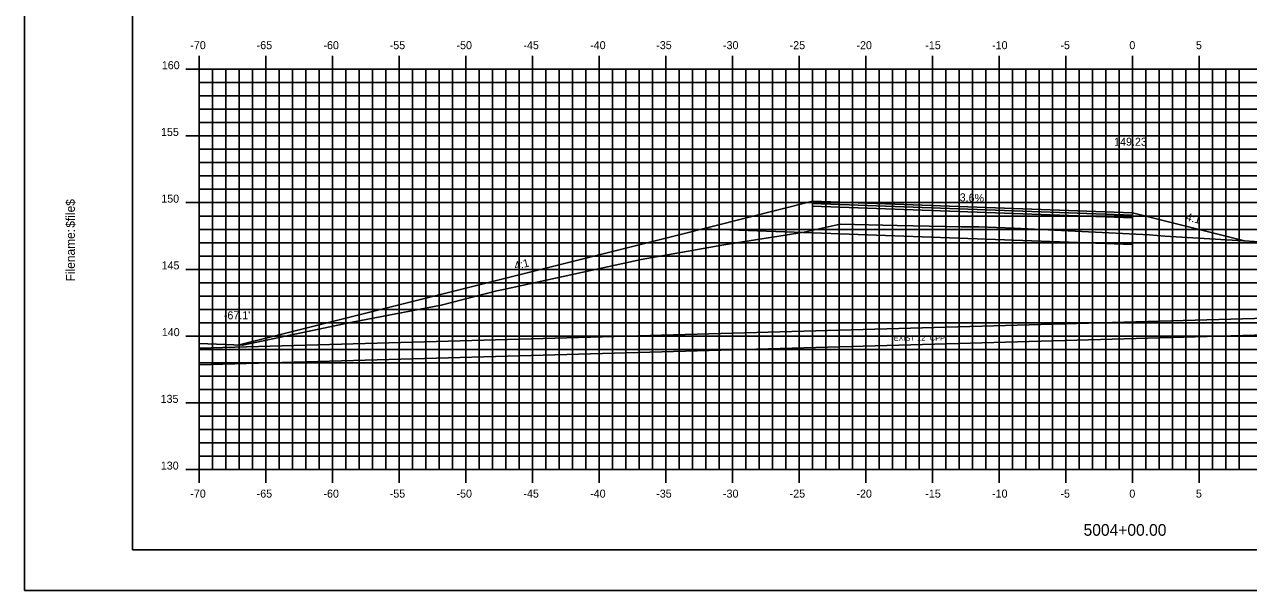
# Model space of a CAD drawing. Extents: x 852082 to 852254, y 365876 to 365986.
# Drawn here: x 852082.1 to 852173.9, y 365875.8 to 365918.2 of the extents above; entities that cross this region are included whole.
import ezdxf

# ---------------------------------------------------------------- set-up
doc = ezdxf.new("R2010")
doc.units = 0
for name, color, linetype in [('ANNOTATION', 7, 'Continuous'), ('BORDER', 7, 'Continuous'), ('D_Drainage_Culvert', 7, 'Continuous'), ('D_Roadway_Centerline', 7, 'Continuous'), ('D_Roadway_Centerline_Text', 7, 'Continuous'), ('D_Roadway_Edge_TW', 7, 'Continuous'), ('D_Roadway_FinishedGrade', 7, 'Continuous'), ('D_Roadway_Pavement', 7, 'Continuous'), ('D_Roadway_SlopeLines', 7, 'Continuous'), ('D_Roadway_SubGrade', 7, 'Continuous'), ('D_Text_Monospaced', 7, 'Continuous'), ('D_Text_Standard', 7, 'Continuous'), ('H_V ANNOTATION', 7, 'Continuous'), ('MAJOR', 7, 'Continuous'), ('MINOR', 7, 'Continuous'), ('PLOT BOUNDARY', 7, 'Continuous'), ('S_Roadway_Centerline', 7, 'Continuous')]:
    doc.layers.add(name, color=color, linetype=linetype)

msp = doc.modelspace()

# ---------------------------------------------------------------- linework, layer by layer
at = {"layer": 'BORDER'}
msp.add_lwpolyline([(852090.168, 365878.833), (852250.168, 365878.833), (852250.168, 365983.833), (852090.168, 365983.833)], close=True, dxfattribs=at)
at = {"layer": 'D_Drainage_Culvert'}
msp.add_lwpolyline([(852095.168, 365892.674), (852204.568, 365895.764), (852204.533, 365897.014), (852095.168, 365893.925)], dxfattribs=at)
at = {"layer": 'D_Roadway_Centerline'}
msp.add_lwpolyline([(852098.064, 365894.159), (852131.168, 365902.435), (852141.168, 365904.935), (852165.168, 365904.067), (852173.559, 365901.969)], dxfattribs=at)
at = {"layer": 'D_Roadway_Edge_TW'}
msp.add_lwpolyline([(852141.168, 365904.935), (852165.168, 365904.067), (852165.168, 365903.9), (852141.168, 365904.768)], close=True, dxfattribs=at)
at = {"layer": 'D_Roadway_FinishedGrade'}
msp.add_line((852141.168, 365902.568), (852132.898, 365902.867), dxfattribs=at)
at = {"layer": 'D_Roadway_Pavement'}
msp.add_lwpolyline([(852141.168, 365904.768), (852165.168, 365903.9), (852165.168, 365903.7), (852141.168, 365904.568)], close=True, dxfattribs=at)
msp.add_lwpolyline([(852165.168, 365903.9), (852165.168, 365903.7)], dxfattribs=at)
msp.add_lwpolyline([(852165.168, 365903.9), (852165.168, 365903.7)], dxfattribs=at)
at = {"layer": 'D_Roadway_SlopeLines'}
for points in [[(852141.168, 365904.935), (852131.168, 365902.435), (852098.064, 365894.159)], [(852165.168, 365904.067), (852173.559, 365901.969)]]:
    msp.add_lwpolyline(points, dxfattribs=at)
at = {"layer": 'D_Roadway_SubGrade'}
msp.add_lwpolyline([(852141.168, 365904.568), (852165.168, 365903.7), (852165.168, 365901.7), (852141.168, 365902.568)], dxfattribs=at)
at = {"layer": 'MAJOR'}
for p, q in [((852095.168, 365915.835), (852095.168, 365914.833)), ((852100.168, 365915.835), (852100.168, 365914.833)), ((852105.168, 365915.835), (852105.168, 365914.833)), ((852110.168, 365915.835), (852110.168, 365914.833)), ((852115.168, 365915.835), (852115.168, 365914.833)), ((852120.168, 365915.835), (852120.168, 365914.833)), ((852125.168, 365915.835), (852125.168, 365914.833)), ((852130.168, 365915.835), (852130.168, 365914.833)), ((852135.168, 365915.835), (852135.168, 365914.833)), ((852140.168, 365915.835), (852140.168, 365914.833)), ((852145.168, 365915.835), (852145.168, 365914.833)), ((852150.168, 365915.835), (852150.168, 365914.833)), ((852155.168, 365915.835), (852155.168, 365914.833)), ((852160.168, 365915.835), (852160.168, 365914.833)), ((852165.168, 365915.835), (852165.168, 365914.833)), ((852170.168, 365915.835), (852170.168, 365914.833)), ((852094.166, 365914.833), (852095.168, 365914.833)), ((852095.168, 365914.833), (852235.168, 365914.833)), ((852095.168, 365884.833), (852095.168, 365914.833)), ((852095.168, 365884.833), (852095.168, 365914.833)), ((852095.168, 365914.833), (852235.168, 365914.833)), ((852100.168, 365884.833), (852100.168, 365914.833)), ((852105.168, 365884.833), (852105.168, 365914.833)), ((852110.168, 365884.833), (852110.168, 365914.833)), ((852115.168, 365884.833), (852115.168, 365914.833)), ((852120.168, 365884.833), (852120.168, 365914.833)), ((852125.168, 365884.833), (852125.168, 365914.833)), ((852130.168, 365884.833), (852130.168, 365914.833)), ((852135.168, 365884.833), (852135.168, 365914.833)), ((852140.168, 365884.833), (852140.168, 365914.833)), ((852145.168, 365884.833), (852145.168, 365914.833)), ((852150.168, 365884.833), (852150.168, 365914.833)), ((852155.168, 365884.833), (852155.168, 365914.833)), ((852160.168, 365884.833), (852160.168, 365914.833)), ((852165.168, 365884.833), (852165.168, 365914.833)), ((852170.168, 365884.833), (852170.168, 365914.833)), ((852094.166, 365909.833), (852095.168, 365909.833)), ((852095.168, 365909.833), (852235.168, 365909.833)), ((852094.166, 365904.833), (852095.168, 365904.833)), ((852095.168, 365904.833), (852235.168, 365904.833)), ((852094.166, 365899.833), (852095.168, 365899.833)), ((852095.168, 365899.833), (852235.168, 365899.833)), ((852094.166, 365894.833), (852095.168, 365894.833)), ((852095.168, 365894.833), (852235.168, 365894.833)), ((852094.166, 365889.833), (852095.168, 365889.833)), ((852095.168, 365889.833), (852235.168, 365889.833)), ((852094.166, 365884.833), (852095.168, 365884.833)), ((852095.168, 365884.833), (852235.168, 365884.833)), ((852095.168, 365884.833), (852235.168, 365884.833)), ((852095.168, 365883.831), (852095.168, 365884.833)), ((852100.168, 365883.831), (852100.168, 365884.833)), ((852105.168, 365883.831), (852105.168, 365884.833)), ((852110.168, 365883.831), (852110.168, 365884.833)), ((852115.168, 365883.831), (852115.168, 365884.833)), ((852120.168, 365883.831), (852120.168, 365884.833)), ((852125.168, 365883.831), (852125.168, 365884.833)), ((852130.168, 365883.831), (852130.168, 365884.833)), ((852135.168, 365883.831), (852135.168, 365884.833)), ((852140.168, 365883.831), (852140.168, 365884.833)), ((852145.168, 365883.831), (852145.168, 365884.833)), ((852150.168, 365883.831), (852150.168, 365884.833)), ((852155.168, 365883.831), (852155.168, 365884.833)), ((852160.168, 365883.831), (852160.168, 365884.833)), ((852165.168, 365883.831), (852165.168, 365884.833)), ((852170.168, 365883.831), (852170.168, 365884.833))]:
    msp.add_line(p, q, dxfattribs=at)
at = {"layer": 'MINOR'}
for p, q in [((852096.168, 365884.833), (852096.168, 365914.833)), ((852097.168, 365884.833), (852097.168, 365914.833)), ((852098.168, 365884.833), (852098.168, 365914.833)), ((852099.168, 365884.833), (852099.168, 365914.833)), ((852101.168, 365884.833), (852101.168, 365914.833)), ((852102.168, 365884.833), (852102.168, 365914.833)), ((852103.168, 365884.833), (852103.168, 365914.833)), ((852104.168, 365884.833), (852104.168, 365914.833)), ((852106.168, 365884.833), (852106.168, 365914.833)), ((852107.168, 365884.833), (852107.168, 365914.833)), ((852108.168, 365884.833), (852108.168, 365914.833)), ((852109.168, 365884.833), (852109.168, 365914.833)), ((852111.168, 365884.833), (852111.168, 365914.833)), ((852112.168, 365884.833), (852112.168, 365914.833)), ((852113.168, 365884.833), (852113.168, 365914.833)), ((852114.168, 365884.833), (852114.168, 365914.833)), ((852116.168, 365884.833), (852116.168, 365914.833)), ((852117.168, 365884.833), (852117.168, 365914.833)), ((852118.168, 365884.833), (852118.168, 365914.833)), ((852119.168, 365884.833), (852119.168, 365914.833)), ((852121.168, 365884.833), (852121.168, 365914.833)), ((852122.168, 365884.833), (852122.168, 365914.833)), ((852123.168, 365884.833), (852123.168, 365914.833)), ((852124.168, 365884.833), (852124.168, 365914.833)), ((852126.168, 365884.833), (852126.168, 365914.833)), ((852127.168, 365884.833), (852127.168, 365914.833)), ((852128.168, 365884.833), (852128.168, 365914.833)), ((852129.168, 365884.833), (852129.168, 365914.833)), ((852131.168, 365884.833), (852131.168, 365914.833)), ((852132.168, 365884.833), (852132.168, 365914.833)), ((852133.168, 365884.833), (852133.168, 365914.833)), ((852134.168, 365884.833), (852134.168, 365914.833)), ((852136.168, 365884.833), (852136.168, 365914.833)), ((852137.168, 365884.833), (852137.168, 365914.833)), ((852138.168, 365884.833), (852138.168, 365914.833)), ((852139.168, 365884.833), (852139.168, 365914.833)), ((852141.168, 365884.833), (852141.168, 365914.833)), ((852142.168, 365884.833), (852142.168, 365914.833)), ((852143.168, 365884.833), (852143.168, 365914.833)), ((852144.168, 365884.833), (852144.168, 365914.833)), ((852146.168, 365884.833), (852146.168, 365914.833)), ((852147.168, 365884.833), (852147.168, 365914.833)), ((852148.168, 365884.833), (852148.168, 365914.833)), ((852149.168, 365884.833), (852149.168, 365914.833)), ((852151.168, 365884.833), (852151.168, 365914.833)), ((852152.168, 365884.833), (852152.168, 365914.833)), ((852153.168, 365884.833), (852153.168, 365914.833)), ((852154.168, 365884.833), (852154.168, 365914.833)), ((852156.168, 365884.833), (852156.168, 365914.833)), ((852157.168, 365884.833), (852157.168, 365914.833)), ((852158.168, 365884.833), (852158.168, 365914.833)), ((852159.168, 365884.833), (852159.168, 365914.833)), ((852161.168, 365884.833), (852161.168, 365914.833)), ((852162.168, 365884.833), (852162.168, 365914.833)), ((852163.168, 365884.833), (852163.168, 365914.833)), ((852164.168, 365884.833), (852164.168, 365914.833)), ((852166.168, 365884.833), (852166.168, 365914.833)), ((852167.168, 365884.833), (852167.168, 365914.833)), ((852168.168, 365884.833), (852168.168, 365914.833)), ((852169.168, 365884.833), (852169.168, 365914.833)), ((852171.168, 365884.833), (852171.168, 365914.833)), ((852172.168, 365884.833), (852172.168, 365914.833)), ((852173.168, 365884.833), (852173.168, 365914.833)), ((852095.168, 365913.833), (852235.168, 365913.833)), ((852095.168, 365913.833), (852096.17, 365913.833)), ((852095.168, 365912.833), (852235.168, 365912.833)), ((852095.168, 365912.833), (852096.17, 365912.833)), ((852095.168, 365911.833), (852235.168, 365911.833)), ((852095.168, 365911.833), (852096.17, 365911.833)), ((852095.168, 365910.833), (852235.168, 365910.833)), ((852095.168, 365910.833), (852096.17, 365910.833)), ((852095.168, 365908.833), (852235.168, 365908.833)), ((852095.168, 365908.833), (852096.17, 365908.833)), ((852095.168, 365907.833), (852235.168, 365907.833)), ((852095.168, 365907.833), (852096.17, 365907.833)), ((852095.168, 365906.833), (852235.168, 365906.833)), ((852095.168, 365906.833), (852096.17, 365906.833)), ((852095.168, 365905.833), (852235.168, 365905.833)), ((852095.168, 365905.833), (852096.17, 365905.833)), ((852095.168, 365903.833), (852235.168, 365903.833)), ((852095.168, 365903.833), (852096.17, 365903.833)), ((852095.168, 365902.833), (852235.168, 365902.833)), ((852095.168, 365902.833), (852096.17, 365902.833)), ((852095.168, 365901.833), (852235.168, 365901.833)), ((852095.168, 365901.833), (852096.17, 365901.833)), ((852095.168, 365900.833), (852235.168, 365900.833)), ((852095.168, 365900.833), (852096.17, 365900.833)), ((852095.168, 365898.833), (852235.168, 365898.833)), ((852095.168, 365898.833), (852096.17, 365898.833)), ((852095.168, 365897.833), (852235.168, 365897.833)), ((852095.168, 365897.833), (852096.17, 365897.833)), ((852095.168, 365896.833), (852235.168, 365896.833)), ((852095.168, 365896.833), (852096.17, 365896.833)), ((852095.168, 365895.833), (852235.168, 365895.833)), ((852095.168, 365895.833), (852096.17, 365895.833)), ((852095.168, 365893.833), (852235.168, 365893.833)), ((852095.168, 365893.833), (852096.17, 365893.833)), ((852095.168, 365892.833), (852235.168, 365892.833)), ((852095.168, 365892.833), (852096.17, 365892.833)), ((852095.168, 365891.833), (852235.168, 365891.833)), ((852095.168, 365891.833), (852096.17, 365891.833)), ((852095.168, 365890.833), (852235.168, 365890.833)), ((852095.168, 365890.833), (852096.17, 365890.833)), ((852095.168, 365888.833), (852235.168, 365888.833)), ((852095.168, 365888.833), (852096.17, 365888.833)), ((852095.168, 365887.833), (852235.168, 365887.833)), ((852095.168, 365887.833), (852096.17, 365887.833)), ((852095.168, 365886.833), (852235.168, 365886.833)), ((852095.168, 365886.833), (852096.17, 365886.833)), ((852095.168, 365885.833), (852235.168, 365885.833)), ((852095.168, 365885.833), (852096.17, 365885.833))]:
    msp.add_line(p, q, dxfattribs=at)
at = {"layer": 'PLOT BOUNDARY'}
msp.add_lwpolyline([(852082.075, 365875.774), (852252.075, 365875.774), (852252.075, 365985.774), (852082.075, 365985.774)], close=True, dxfattribs=at)
at = {"layer": 'S_Roadway_Centerline'}
msp.add_lwpolyline([(852095.168, 365894.275), (852098.427, 365894.144), (852106.658, 365895.867), (852113.325, 365897.157), (852117.505, 365898.216), (852117.991, 365898.323), (852128.33, 365900.575), (852134.515, 365901.68), (852140.531, 365902.632), (852143.245, 365903.216), (852147.519, 365903.122), (852152.325, 365903.031), (852153.64, 365903.026), (852156.302, 365902.922), (852161.358, 365902.66), (852166.428, 365902.412), (852167.58, 365902.33), (852175.592, 365901.847)], dxfattribs=at)

# ---------------------------------------------------------------- texts
at = {"layer": 'ANNOTATION'}
for s, rotation, p in [('3.6%', 357.92852, (852152.194, 365904.937)), ('4:1', 345.96376, (852169.116, 365903.511)), ('4:1', 14.03624, (852118.884, 365899.795))]:
    msp.add_text(s, height=0.6, rotation=rotation, dxfattribs=at).set_placement(p)
at = {"layer": 'BORDER'}
for s, p in [('$file$', (852085.853, 365902.959)), ('Filename:', (852085.853, 365898.932))]:
    msp.add_text(s, height=0.6696, rotation=90, dxfattribs=at).set_placement(p)
at = {"layer": 'D_Roadway_Centerline_Text'}
msp.add_text('149.23', height=0.6, dxfattribs=at).set_placement((852163.785, 365909.099))
at = {"layer": 'D_Text_Monospaced'}
msp.add_text('EXIST 12" CPP', height=0.39998, dxfattribs=at).set_placement((852147.257, 365894.494))
at = {"layer": 'D_Text_Standard'}
msp.add_text("-67.1'", height=0.6, dxfattribs=at).set_placement((852097.024, 365896.095))
at = {"layer": 'H_V ANNOTATION'}
for s, height, p in [('-70', 0.6, (852094.51, 365916.333)), ('-65', 0.6, (852099.486, 365916.333)), ('-60', 0.6, (852104.494, 365916.333)), ('-55', 0.6, (852109.464, 365916.333)), ('-50', 0.6, (852114.472, 365916.333)), ('-45', 0.6, (852119.486, 365916.333)), ('-40', 0.6, (852124.494, 365916.333)), ('-35', 0.6, (852129.448, 365916.333)), ('-30', 0.6, (852134.456, 365916.333)), ('-25', 0.6, (852139.454, 365916.333)), ('-20', 0.6, (852144.462, 365916.333)), ('-15', 0.6, (852149.625, 365916.333)), ('-10', 0.6, (852154.633, 365916.333)), ('-5', 0.6, (852159.759, 365916.333)), ('0', 0.6, (852164.927, 365916.333)), ('5', 0.6, (852169.919, 365916.333)), ('160', 0.6, (852092.373, 365914.833)), ('155', 0.6, (852092.314, 365909.833)), ('150', 0.6, (852092.33, 365904.833)), ('145', 0.6, (852092.357, 365899.833)), ('140', 0.6, (852092.373, 365894.833)), ('135', 0.6, (852092.282, 365889.833)), ('130', 0.6, (852092.298, 365884.833)), ('-70', 0.6, (852094.51, 365882.733)), ('-65', 0.6, (852099.486, 365882.733)), ('-60', 0.6, (852104.494, 365882.733)), ('-55', 0.6, (852109.464, 365882.733)), ('-50', 0.6, (852114.472, 365882.733)), ('-45', 0.6, (852119.486, 365882.733)), ('-40', 0.6, (852124.494, 365882.733)), ('-35', 0.6, (852129.448, 365882.733)), ('-30', 0.6, (852134.456, 365882.733)), ('-25', 0.6, (852139.454, 365882.733)), ('-20', 0.6, (852144.462, 365882.733)), ('-15', 0.6, (852149.625, 365882.733)), ('-10', 0.6, (852154.633, 365882.733)), ('-5', 0.6, (852159.759, 365882.733)), ('0', 0.6, (852164.927, 365882.733)), ('5', 0.6, (852169.919, 365882.733)), ('5004+00.00', 0.875, (852161.493, 365879.876))]:
    msp.add_text(s, height=height, dxfattribs=at).set_placement(p)
at = {"layer": 'MAJOR'}
msp.add_text('-', height=0.006, dxfattribs=at).set_placement((852095.164, 365884.833))

doc.saveas('drawing.dxf')
